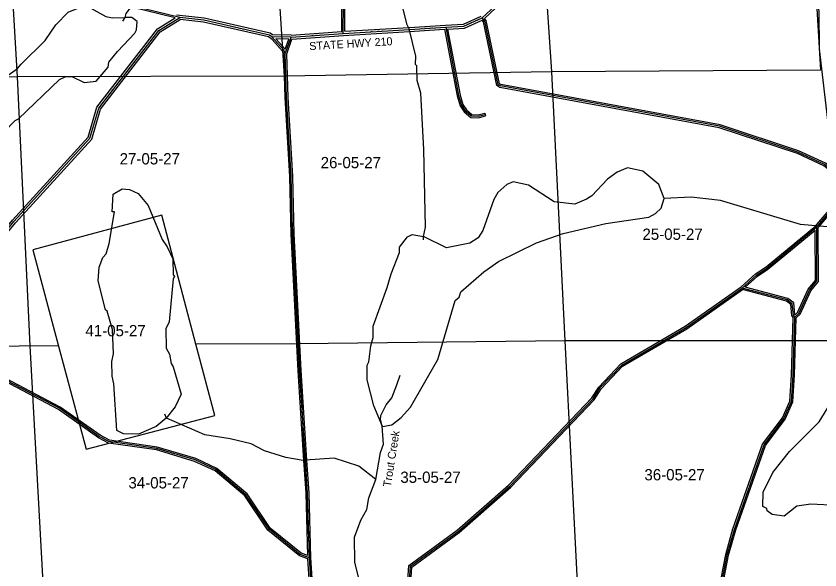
# Model space of a CAD drawing. Extents: x 418523 to 616617, y 1878279 to 2196743.
# Drawn here: x 470862 to 486921, y 2066699 to 2077753 of the extents above; entities that cross this region are included whole.
import ezdxf

# ---------------------------------------------------------------- set-up
doc = ezdxf.new("R2010")
doc.units = 0
for name, color, linetype in [('Level 1', 7, 'Continuous'), ('Level 2', 7, 'Continuous'), ('Level 22', 7, 'Continuous'), ('Level 23', 7, 'Continuous'), ('Level 28', 7, 'Continuous'), ('Level 31', 7, 'Continuous'), ('Level 32', 7, 'Continuous'), ('Level 34', 7, 'Continuous'), ('Level 41', 7, 'Continuous'), ('Level 5', 7, 'Continuous'), ('Level 7', 7, 'Continuous')]:
    doc.layers.add(name, color=color, linetype=linetype)

msp = doc.modelspace()

# ---------------------------------------------------------------- linework, layer by layer
at = {"layer": 'Level 1'}
for p, q in [((486606.202, 2082081.516), (486931.769, 2076675.421)), ((470573.957, 2081856.326), (470884.124, 2076542.318)), ((475890.106, 2081933.551), (476215.832, 2076553.452)), ((481567.974, 2076640.471), (481200.118, 2081986.811)), ((470884.124, 2076542.318), (469176.251, 2076520.481)), ((476215.832, 2076553.452), (470884.124, 2076542.318)), ((470884.124, 2076542.318), (471138.041, 2071170.632)), ((481567.974, 2076640.471), (476215.832, 2076553.452)), ((476215.832, 2076553.452), (476503.859, 2071209.572)), ((486931.769, 2076675.421), (481567.974, 2076640.471)), ((481829.892, 2071270.743), (481567.974, 2076640.471)), ((473773.221, 2073777.482), (471199.913, 2073088.351)), ((474453.843, 2071205.424), (473773.221, 2073777.482)), ((471199.913, 2073088.351), (471712.612, 2071163.43)), ((481829.892, 2071270.743), (476503.859, 2071209.572)), ((487227.421, 2071273.497), (481829.892, 2071270.743)), ((482107.939, 2065926.923), (481829.892, 2071270.743)), ((471138.041, 2071170.632), (465857.368, 2071021.196)), ((471712.612, 2071163.43), (471138.041, 2071170.632)), ((471138.041, 2071170.632), (471437.468, 2065734.681)), ((471712.612, 2071163.43), (472258.991, 2069112.061)), ((476503.859, 2071209.572), (474453.843, 2071205.424)), ((474830.192, 2069783.204), (474453.843, 2071205.424)), ((476503.859, 2071209.572), (476783.714, 2065835.738)), ((472258.991, 2069112.061), (474830.192, 2069783.204))]:
    msp.add_line(p, q, dxfattribs=at)
at = {"layer": 'Level 22'}
for p, q in [((480176.445, 2077719.599), (482597.001, 2080033.696)), ((478719.492, 2077488.48), (479444.934, 2077532.583)), ((476356.335, 2077329.908), (475972.886, 2077339.811)), ((476356.335, 2077329.908), (477399.004, 2077408.041)), ((477399.004, 2077408.041), (478719.492, 2077488.48))]:
    msp.add_line(p, q, dxfattribs=at)
for points in [[(468983.871, 2071580.223), (470174.144, 2072883.373), (470819.545, 2073655.448), (472336.789, 2075315.229), (472514.811, 2075914.771), (473714.296, 2077467.838), (474132.622, 2077724.317)], [(475972.886, 2077339.811), (475923.059, 2077373.516), (474615.842, 2077671.708), (474132.622, 2077724.317)], [(479444.934, 2077532.583), (479808.92, 2077554.816), (480176.445, 2077719.599)]]:
    msp.add_lwpolyline(points, dxfattribs=at)
at = {"layer": 'Level 23'}
for p, q in [((480222.349, 2077708.142), (482624.243, 2080004.396)), ((477429.19, 2077449.954), (478717.06, 2077528.407)), ((478717.064, 2077528.407), (479442.506, 2077572.51)), ((476355.356, 2077369.946), (475985.611, 2077379.496)), ((476355.356, 2077369.946), (477369.169, 2077445.917)), ((476374.127, 2077291.127), (477401.994, 2077368.151)), ((477401.994, 2077368.151), (478721.924, 2077448.552)), ((478721.92, 2077448.552), (479422.223, 2077491.126)), ((476310.244, 2077291.084), (476050.942, 2077297.78))]:
    msp.add_line(p, q, dxfattribs=at)
for points in [[(468984.533, 2071640.259), (470144.017, 2072909.701), (470789.424, 2073681.783), (472301.06, 2075335.431), (472478.589, 2075933.313), (473687.127, 2077498.101), (474041.879, 2077715.601)], [(469038.019, 2071580.191), (470204.271, 2072857.045), (470849.667, 2073629.113), (472372.518, 2075295.027), (472551.032, 2075896.228), (473741.466, 2077437.575), (474141.879, 2077683.071)], [(475985.611, 2077379.496), (475939.262, 2077410.849), (474622.477, 2077711.224), (474063.544, 2077772.075)], [(475980.633, 2077286.277), (475906.854, 2077336.185), (474609.208, 2077632.193), (474141.88, 2077683.071)], [(479442.494, 2077572.51), (479799.206, 2077594.299), (480153.788, 2077753.277)], [(479482.588, 2077494.806), (479818.634, 2077515.333), (480172.856, 2077674.15)]]:
    msp.add_lwpolyline(points, dxfattribs=at)
at = {"layer": 'Level 31'}
for p, q in [((474132.622, 2077724.317), (473173.479, 2077958.626)), ((476237.969, 2077005.361), (476356.335, 2077329.908)), ((486858.633, 2073543.658), (486882.814, 2073571.913)), ((476791.934, 2065831.724), (476722.392, 2066940.571))]:
    msp.add_line(p, q, dxfattribs=at)
for points in [[(477399.004, 2077408.041), (477401.683, 2078016.471), (477378.042, 2078291.896), (477366.679, 2079325.542), (477442.937, 2079583.746), (477458.564, 2079608.764)], [(487321.844, 2074549.99), (487014.764, 2074793.268), (486482.389, 2075037.6), (484917.509, 2075553.738), (480536.591, 2076359.133), (480494.944, 2076384.065), (480226.114, 2077652.804), (480176.445, 2077719.599)], [(479444.934, 2077532.583), (479701.889, 2076170.066), (479759.485, 2075975.943), (479835.187, 2075861.015), (479957.474, 2075760.407), (480097.619, 2075753.181), (480232.277, 2075789.261)], [(476237.969, 2077005.361), (476213.303, 2077072.037), (475972.886, 2077339.811)], [(476643.381, 2068887.028), (476524.048, 2070676.576), (476387.211, 2073403.06), (476359.361, 2074553.529), (476267.173, 2076129.828), (476237.969, 2077005.361)], [(486882.814, 2073571.913), (487177.135, 2073917.131), (487187.539, 2074317.131), (487321.844, 2074549.99)], [(485368.758, 2072325.392), (485653.513, 2072582.631), (485862.4, 2072723.124), (486858.633, 2073543.658)], [(486416.379, 2071745.136), (486499.959, 2071819.665), (486710.681, 2072285.647), (486861.534, 2072468.239), (486858.633, 2073543.658)], [(478667.134, 2065730.87), (478739.003, 2066772.468), (479692.859, 2067467.911), (480722.695, 2068371.765), (482390.097, 2070114.152), (482524.368, 2070330.265), (482960.119, 2070786.787), (484247.614, 2071538.946), (485368.758, 2072325.392)], [(486416.379, 2071745.136), (486391.575, 2071787.076), (486367.624, 2072011.943), (486267.976, 2072087.691), (485368.758, 2072325.392)], [(484912.574, 2065975.121), (484922.924, 2066425.31), (484973.364, 2066516.719), (485067.424, 2066999.971), (485211.608, 2067507.719), (485803.471, 2069197.146), (486198.046, 2069720.454), (486349.653, 2070061.606), (486385.651, 2070586.592), (486416.379, 2071745.136)], [(476722.392, 2066940.571), (476539.468, 2067008.393), (475916.54, 2067511.542), (475453.105, 2068197.567), (474855.216, 2068700.611), (474439.362, 2068894.35), (473673.646, 2069122.944), (472715.693, 2069261.242), (472524.409, 2069362.221), (471726.861, 2069924.516), (470521.115, 2070555.833), (468983.871, 2071580.223)], [(476722.392, 2066940.571), (476686.993, 2068232.911), (476643.381, 2068887.028)]]:
    msp.add_lwpolyline(points, dxfattribs=at)
at = {"layer": 'Level 32'}
for p, q in [((474041.879, 2077715.601), (473166.361, 2077929.482)), ((476237.075, 2077090.465), (476050.941, 2077297.78)), ((476237.075, 2077090.465), (476310.244, 2077291.083)), ((476268.148, 2077000.546), (476374.127, 2077291.127)), ((480224.513, 2075818.24), (480240.04, 2075760.281)), ((486837.541, 2073565.152), (486860.022, 2073591.42)), ((486888.664, 2073532.607), (486905.608, 2073552.405)), ((476759.432, 2065870.684), (476693.671, 2066919.223)), ((476819.481, 2065871.802), (476752.368, 2066941.921))]:
    msp.add_line(p, q, dxfattribs=at)
for points in [[(487282.597, 2074619.356), (487252.714, 2074849.777), (487153.572, 2075050.793), (486912.625, 2077101.132), (486907.901, 2077850.298), (486848.24, 2078157.194), (486824.679, 2078157.304), (486721.514, 2078560.501), (486669.751, 2078665.276), (486697.148, 2079033.536), (486776.511, 2079463.126), (487486.574, 2079992.492), (487555.426, 2080661.981), (487640.854, 2081827.687)], [(477369.17, 2077445.918), (477371.676, 2078015.252), (477348.056, 2078290.446), (477336.63, 2079329.719), (477415.324, 2079596.169), (477433.119, 2079624.657)], [(477429.19, 2077449.954), (477431.689, 2078017.69), (477408.029, 2078293.346), (477396.727, 2079321.366), (477470.549, 2079571.324), (477484.009, 2079592.871)], [(487282.921, 2074542.551), (486998.966, 2074767.508), (486471.399, 2075009.634), (484910.064, 2075524.603), (480525.834, 2076330.607), (480468.306, 2076365.045), (480198.126, 2077640.166), (480172.855, 2077674.15)], [(487282.597, 2074619.356), (487030.56, 2074819.027), (486493.378, 2075065.566), (484924.954, 2075582.874), (480547.349, 2076387.659), (480521.58, 2076403.085), (480254.104, 2077665.441), (480222.349, 2077708.143)], [(479482.588, 2077494.806), (479731.086, 2076177.131), (479786.983, 2075988.736), (479857.748, 2075881.303), (479968.896, 2075789.86), (480094.431, 2075783.386), (480224.513, 2075818.24)], [(479422.223, 2077491.126), (479672.691, 2076163.001), (479731.987, 2075963.151), (479812.626, 2075840.726), (479946.052, 2075730.956), (480100.805, 2075722.977), (480240.04, 2075760.281)], [(476208.148, 2076999.506), (476187.153, 2077056.256), (475980.632, 2077286.277)], [(476613.448, 2068885.031), (476494.097, 2070674.826), (476357.229, 2073401.945), (476329.382, 2074552.291), (476237.201, 2076128.451), (476208.148, 2076999.506)], [(476673.315, 2068889.024), (476553.999, 2070678.325), (476417.194, 2073404.174), (476389.341, 2074554.768), (476297.144, 2076131.204), (476268.149, 2077000.546)], [(486859.984, 2073591.377), (487147.421, 2073928.518), (487157.747, 2074325.524), (487282.921, 2074542.551)], [(486905.644, 2073552.448), (487206.849, 2073905.742), (487217.332, 2074308.74), (487330.332, 2074504.658)], [(485350.019, 2072348.891), (485634.992, 2072606.33), (485844.45, 2072747.206), (486837.542, 2073565.152)], [(485429.955, 2072340.245), (485672.034, 2072558.932), (485880.35, 2072699.041), (486828.804, 2073480.222)], [(486423.635, 2071791.801), (486475.244, 2071837.822), (486684.998, 2072301.663), (486831.504, 2072478.994), (486828.804, 2073480.222)], [(486446.026, 2071731.376), (486524.673, 2071801.507), (486736.364, 2072269.631), (486891.564, 2072457.485), (486888.664, 2073532.607)], [(478640.408, 2065779.341), (478710.035, 2066788.476), (479674.089, 2067491.354), (480701.924, 2068393.451), (482366.263, 2070132.638), (482500.522, 2070348.734), (482941.335, 2070810.559), (484231.404, 2071564.222), (485350.018, 2072348.891)], [(478698.918, 2065755.668), (478767.97, 2066756.46), (479711.629, 2067444.468), (480743.467, 2068350.079), (482413.931, 2070095.666), (482548.213, 2070311.796), (482978.903, 2070763.015), (484263.823, 2071513.67), (485374.572, 2072292.823)], [(486386.161, 2071737.296), (486362.434, 2071777.415), (486339.164, 2071995.893), (486254.557, 2072060.206), (485374.572, 2072292.823)], [(486423.635, 2071791.801), (486420.716, 2071796.736), (486396.086, 2072027.993), (486281.395, 2072115.175), (485429.955, 2072340.246)], [(484882.589, 2065976.095), (484893.1, 2066433.358), (484944.817, 2066527.082), (485038.219, 2067006.948), (485182.995, 2067516.785), (485776.703, 2069211.476), (486172.024, 2069735.775), (486320.085, 2070068.945), (486355.678, 2070588.016), (486386.161, 2071737.297)], [(484943.284, 2066005.602), (484952.747, 2066417.261), (485001.91, 2066506.356), (485096.63, 2066992.996), (485240.22, 2067498.653), (485830.239, 2069182.816), (486224.068, 2069705.133), (486379.22, 2070054.266), (486415.624, 2070585.167), (486446.027, 2071731.375)], [(476691.187, 2066984.137), (476554.5, 2067034.816), (475938.886, 2067532.058), (475475.623, 2068217.829), (474871.489, 2068726.126), (474450.044, 2068922.47), (473680.115, 2069152.322), (472725.112, 2069290.194), (472540.12, 2069387.852), (471742.53, 2069950.176), (470536.434, 2070581.677), (469038.019, 2071580.191)], [(476693.671, 2066919.223), (476524.435, 2066981.97), (475894.195, 2067491.026), (475430.589, 2068177.306), (474838.944, 2068675.095), (474428.679, 2068866.23), (473667.178, 2069093.566), (472706.273, 2069232.291), (472508.699, 2069336.591), (471711.192, 2069898.856), (470505.797, 2070529.99), (469000.274, 2071533.241)], [(476691.187, 2066984.137), (476657.019, 2068231.502), (476613.448, 2068885.032)], [(476752.368, 2066941.921), (476716.966, 2068234.32), (476673.315, 2068889.023)]]:
    msp.add_lwpolyline(points, dxfattribs=at)
at = {"layer": 'Level 5'}
for p, q in [((472996.88, 2077649.191), (473038.949, 2077723.983)), ((479000.433, 2073289.866), (479000.802, 2073356.558))]:
    msp.add_line(p, q, dxfattribs=at)
for points in [[(473038.949, 2077723.983), (473064.419, 2077807.216), (473375.119, 2078222.331), (473592.851, 2078404.559), (474557.774, 2079549.773), (475001.699, 2079930.82), (475628.269, 2080177.505), (476370.794, 2080281.858), (476805.46, 2080496.25)], [(479000.802, 2073356.558), (479043.489, 2073539.724), (479010.223, 2075090.495), (478949.682, 2076216.264), (478875.996, 2076466.75), (478869.261, 2076758.587), (478844.38, 2076783.728), (478845.267, 2076950.452), (478714.895, 2077501.376), (478673.603, 2077576.636), (478591.975, 2077893.844), (478319.591, 2078395.534), (478195.365, 2078546.276)], [(487972.387, 2073632.861), (487521.538, 2073510.271), (486529.934, 2073590.7), (484931.968, 2074074.581), (484348.754, 2074136.114), (483806.761, 2074114.056)], [(478177.59, 2069567.931), (478144.679, 2069697.926), (478145.731, 2069783.386), (478254.68, 2069993.426), (478368.019, 2070130.706), (478467.089, 2070391.71), (478533.233, 2070585.956)], [(476643.381, 2068887.028), (476598.423, 2068883.614), (476248.68, 2068943.897), (475824.302, 2069079.109), (475558.169, 2069213.903), (475141.86, 2069315.988), (474633.649, 2069393.443), (473868.173, 2069730.775), (473835.318, 2069805.858)], [(478047.352, 2068501.524), (478141.471, 2069042.951), (478200.836, 2069209.226), (478177.59, 2069567.931)], [(478047.352, 2068501.524), (477706.854, 2068769.774), (477215.816, 2068930.756), (476643.381, 2068887.028)], [(477713.018, 2066479.271), (477712.345, 2066535.646), (477630.619, 2066844.451), (477624.888, 2067353.27), (477751.581, 2067694.146), (477869.073, 2067901.959), (477911.995, 2068135.232), (478047.352, 2068501.524)]]:
    msp.add_lwpolyline(points, dxfattribs=at)
at = {"layer": 'Level 7'}
for points in [[(469647.806, 2074991.371), (469531.293, 2075025.371), (469390.556, 2075209.524), (469299.871, 2075393.418), (469309.289, 2075593.463), (469644.281, 2075875.066), (470305.14, 2076296.646), (470890.947, 2076710.266), (470966.427, 2076793.229), (471444.19, 2077265.819), (471654.33, 2077581.461), (471905.762, 2077830.171), (472114.665, 2077920.766), (472356.381, 2077911.119), (472655.58, 2077742.748), (472788.824, 2077717.02), (473038.949, 2077723.983)], [(469647.806, 2074991.371), (469789.29, 2074948.942), (470047.626, 2074930.856), (470156.229, 2074971.948), (470843.603, 2075668.476), (470910.494, 2075701.459), (471731.74, 2076488.961), (471857.112, 2076546.635), (471973.824, 2076545.976), (472223.252, 2076427.926), (472465.138, 2076451.631), (472700.099, 2076733.791), (472717.327, 2076833.725), (472885.228, 2077049.553), (473237.349, 2077414.457), (473271.059, 2077480.95), (473280.277, 2077647.645), (473172.333, 2077723.265), (473038.949, 2077723.983)], [(483806.761, 2074114.056), (483699.854, 2074389.741), (483384.552, 2074658.204), (483076.464, 2074726.571), (482867.56, 2074636.016), (482675.038, 2074495.34), (482364.796, 2074163.557), (482256.065, 2074097.454), (482022.121, 2073998.698), (481613.871, 2074042.603), (481098.814, 2074378.875), (480790.735, 2074447.232), (480665.393, 2074389.569), (480489.482, 2074232.122), (480405.332, 2074090.867), (480185.247, 2073475.148), (480092.728, 2073325.623), (479925.415, 2073218.127), (479458.086, 2073128.988), (479000.802, 2073356.558)], [(478179.856, 2069559.555), (478371.76, 2069591.878), (478555.982, 2069740.925), (478740.523, 2069948.353), (479287.52, 2070895.716), (479635.758, 2072077.623), (479711.149, 2072143.886), (479745.078, 2072252.089), (480205.742, 2072649.716), (480498.655, 2072856.556), (481259.297, 2073227.566), (481793.866, 2073416.389), (482645.253, 2073611.816), (483504.59, 2073740.551), (483638.392, 2073814.856), (483747.353, 2073922.61), (483806.761, 2074114.056)], [(478179.856, 2069559.555), (478007.055, 2069977.323), (477876.484, 2070494.896), (477878.089, 2070786.673), (477911.799, 2070853.196), (477946.844, 2071169.785), (477997.782, 2071336.25), (477998.989, 2071561.326), (478278.312, 2072335.111), (478354.839, 2072609.779), (478523.856, 2073034.023), (478524.444, 2073142.396), (478683.984, 2073349.954), (478775.916, 2073391.116), (479000.802, 2073356.558)], [(487249.748, 2067984.632), (486741.365, 2068012.416), (486457.699, 2067972.281), (486206.527, 2067773.582), (485964.97, 2067808.23), (485865.287, 2067875.45), (485857.216, 2067925.531), (485782.414, 2067967.611), (485783.959, 2068251.048), (485977.816, 2068641.801), (486313.597, 2069065.157), (486908.681, 2069653.801), (487194.639, 2070119.098)]]:
    msp.add_lwpolyline(points, dxfattribs=at)
msp.add_lwpolyline([(473862.442, 2069724.767), (473661.459, 2069559.121), (473310.544, 2069411.001), (473010.437, 2069412.637), (472877.413, 2069480.047), (472815.795, 2070414.051), (472783.273, 2070564.305), (472776.538, 2070856.113), (472810.735, 2071014.337), (472788.337, 2071497.951), (472681.959, 2071865.339), (472648.747, 2071890.539), (472501.834, 2072466.573), (472520.01, 2072741.571), (472596.089, 2072932.886), (472663.169, 2073007.55), (472722.667, 2073215.636), (472826.139, 2073848.645), (472784.458, 2073848.874), (472803.033, 2074198.904), (472978.685, 2074306.33), (473128.639, 2074288.831), (473303.314, 2074212.861), (473502.043, 2073970.028), (473781.81, 2073293.233), (473881.095, 2073150.991), (473996.462, 2072908.586), (474003.098, 2072591.767), (474027.909, 2072558.296), (474002.639, 2072508.405), (473922.931, 2071650.181), (473855.492, 2071508.826), (473861.729, 2071125.316), (473927.772, 2071008.253), (473960.106, 2070816.319), (474001.388, 2070749.427), (474156.841, 2070206.675), (474038.782, 2069957.246), (473862.442, 2069724.767)], close=True, dxfattribs=at)

# ---------------------------------------------------------------- texts
at = {"layer": 'Level 2'}
for s, p in [('27-05-27', (472931.414, 2074792.998)), ('26-05-27', (476947.146, 2074716.671)), ('25-05-27', (483374.862, 2073287.177)), ('41-05-27', (472247.295, 2071362.821)), ('35-05-27', (478538.772, 2068436.285)), ('36-05-27', (483414.794, 2068486.595)), ('34-05-27', (473106.635, 2068325.726))]:
    msp.add_text(s, height=225, dxfattribs=at).set_placement(p)
at = {"layer": 'Level 28'}
msp.add_text('STATE HWY 210', height=160, rotation=3.4781777, dxfattribs=at).set_placement((476723.744, 2077072.924))
at = {"layer": 'Level 34'}
for height, rotation, p in [(25, 24.1486, (479883.986, 2077574.776)), (25, 347.1492973, (475145.069, 2077538.166)), (25, 3.4781777, (478958.475, 2077490.488)), (25, 4.2846611, (476754.226, 2077347.191)), (24.99916, 3.4851667, (477935.524, 2077428.204)), (25, 47.5678472, (471503.239, 2074384.85))]:
    msp.add_text('STATE HWY 210', height=height, rotation=rotation, dxfattribs=at).set_placement(p)
at = {"layer": 'Level 41'}
msp.add_text('Trout Creek', height=160, rotation=81.0838028, dxfattribs=at).set_placement((478349.564, 2068347.348))

doc.saveas('drawing.dxf')
